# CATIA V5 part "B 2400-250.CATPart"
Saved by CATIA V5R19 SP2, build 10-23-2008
Part number: B 2400-250
Bounding box of the stored display mesh (mm): x -37.351 to 37.351, y -37.351 to 37.351, z 0 to 610
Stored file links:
  C:\Users\Bora\Desktop\3D Katı model\B serisi\B 2400\B 2400-250.CATPart
  C:\Program Files\Dassault Systemes\B19\intel_a\reffiles\standard\MetricThickPitch.txt
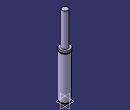
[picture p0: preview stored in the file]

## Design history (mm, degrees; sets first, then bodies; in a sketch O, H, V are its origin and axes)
Body1 (main body)
  Sketch1 on yz-plane, origin (0, 0, 0), H (0, 1, 0), V (0, 0, 1)
    point P3 (22.5, 609)
    point P5 (22.5, 609)
    point P10 (37.5, 336.5)
    point P11 (37.5, 341.5)
    point P13 (37.5, 341.5)
    point P14 (37.5, 336.5)
    line L1 (37.5, 0) -> (37.5, 8)
    line L2 (22.5, 609) -> (22.5, 357)
    arc A1 centre (21.5, 609) radius 1 from (22.5, 609) to (21.5, 610) ccw
    line L3 (33.5, 13) -> (33.5, 8)
    line L4 (37.5, 13) -> (37.5, 336.5)
    line L5 (37.5, 341.5) -> (37.5, 357)
    arc A2 centre (37.5, 339) radius 2.5 from (37.5, 341.5) to (37.5, 336.5) ccw
    line L6 (21.5, 610) -> (0, 610)
    point P15 (0, 610)
    line L7 (22.5, 357) -> (37.5, 357)
    line L8 (0, 0) -> (37.5, 0)
    line L9 (33.5, 13) -> (37.5, 13)
    line L10 (33.5, 8) -> (37.5, 8)
    coincidence: P15 V, P3 P5, P10 P14, P11 P13
    tangency: L6 A1
    horizontal: L7 H, L8 H, L9 H, L10 H
  Shaft1: profile Sketch1, axis Sketch1.V, angle 360
  Sketch2 on face of Shaft1 from Sketch1.L8, origin (0, 0, 0), H (1, 0, 0), V (0, -1, 0)
    point P1 (20, 0)
    distance P1 V = 20
  Hole1: placed by Sketch2, at (20, 0, 0) direction (0, 0, 1), diameter 6.647, depth 13, threaded "M8", thread diameter 8, thread depth 13, pitch 1.25
  CircPattern1: of Hole1, instances 4, angular step 90, axis from xy-plane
